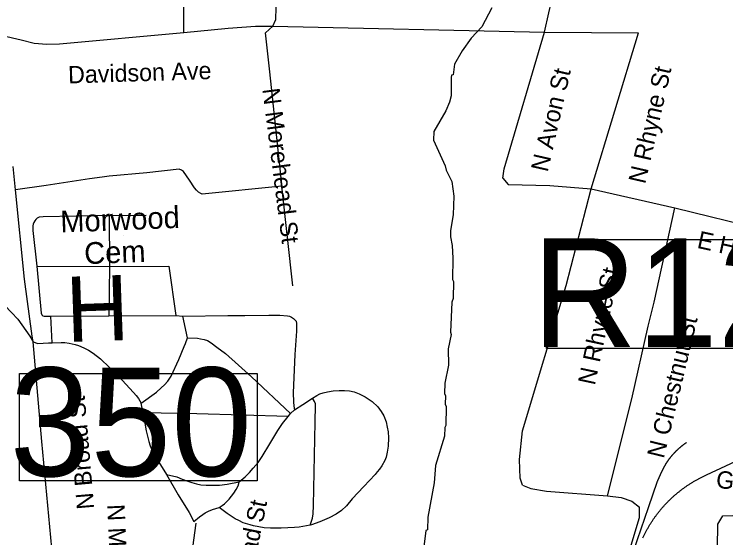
# Model space of a CAD drawing. Extents: x 1268485 to 1426702, y 514839 to 616766.
# Drawn here: x 1350047 to 1352734, y 560205 to 562181 of the extents above; entities that cross this region are included whole.
import ezdxf

# ---------------------------------------------------------------- set-up
doc = ezdxf.new("R2010")
doc.units = 0
for name, color, linetype in [('Old_Level_10', 7, 'Continuous'), ('Old_Level_22', 7, 'Continuous'), ('Old_Level_31', 7, 'Continuous'), ('Old_Level_35', 7, 'Continuous'), ('Old_Level_44', 7, 'Continuous'), ('Old_Level_62', 7, 'Continuous')]:
    doc.layers.add(name, color=color, linetype=linetype)

msp = doc.modelspace()

# ---------------------------------------------------------------- linework, layer by layer
at = {"layer": 'Old_Level_22'}
msp.add_line((1350461.386, 561344.686), (1350461.386, 561344.686), dxfattribs=at)
at = {"layer": 'Old_Level_31'}
for points in [[(1352056.755, 561330.524), (1353320.503, 561330.524), (1353320.503, 560920.201), (1352056.755, 560920.201), (1352056.755, 561330.524)], [(1350067.77, 560825.227), (1350964.648, 560825.227), (1350964.648, 560420.886), (1350067.77, 560420.886), (1350067.77, 560825.227)]]:
    msp.add_lwpolyline(points, dxfattribs=at)
at = {"layer": 'Old_Level_35'}
for p, q in [((1351023.791, 562136.395), (1352049.462, 562113.275)), ((1352049.462, 562113.275), (1352403.894, 562111.379)), ((1352225.089, 561522.007), (1352403.894, 562111.379)), ((1350052.767, 561518.163), (1350043.847, 561606.386)), ((1351098.738, 561156.194), (1351057.727, 561531.85)), ((1352131.483, 561157.374), (1352225.089, 561522.007)), ((1352225.089, 561522.007), (1352541.792, 561450.137)), ((1350405.764, 561421.327), (1350544.995, 561423.48)), ((1352463.359, 561094.115), (1352541.792, 561450.137)), ((1350405.764, 561421.327), (1350406.79, 561229.757)), ((1350132.84, 561230.372), (1350406.79, 561229.757)), ((1350406.79, 561229.757), (1350404.739, 561043.108)), ((1350406.79, 561229.757), (1350631.527, 561230.68)), ((1350631.527, 561230.68), (1350657.978, 561043.775)), ((1352440.291, 561004.508), (1352463.359, 561094.115)), ((1350185.128, 561041.775), (1350404.739, 561043.108)), ((1350191.075, 560941.505), (1350185.128, 561041.775)), ((1350404.739, 561043.108), (1350657.978, 561043.775)), ((1350657.978, 561043.775), (1350683.917, 561041.98)), ((1350701.142, 560960.575), (1350683.917, 561041.98)), ((1350534.742, 560677.039), (1350526.232, 560713.692)), ((1351081.103, 560663.454), (1351090.331, 560674.989)), ((1351090.331, 560674.989), (1351104.992, 560687.753)), ((1350708.524, 560071.982), (1350734.463, 560260.476))]:
    msp.add_line(p, q, dxfattribs=at)
for points in [[(1350687.301, 562112.455), (1350687.301, 562306.178), (1350694.478, 562365.541), (1350708.114, 562428.082), (1350736.206, 562519.688), (1350750.764, 562568.696), (1350760.094, 562614.525), (1350768.501, 562710.336), (1350782.035, 562979.057)], [(1352049.462, 562113.275), (1352065.353, 562186.376), (1352073.76, 562223.901), (1352093.548, 562326.991), (1352106.979, 562417.624), (1352113.233, 562461.351), (1352120.615, 562528.045), (1352121.127, 562567.517), (1352119.487, 562606.169), (1352105.954, 562659.329)], [(1351023.791, 562136.395), (1351035.172, 562161.36), (1351039.375, 562343.703), (1351046.655, 562382.201), (1351083.154, 562478.063)], [(1350687.301, 562112.455), (1350855.033, 562129.064), (1350958.175, 562136.395), (1351023.791, 562136.395)], [(1351057.727, 561531.85), (1351057.01, 561538.463), (1351012.206, 561963.434), (1350995.597, 562110.302), (1351023.791, 562136.395)], [(1350003.247, 562101.126), (1350072.965, 562084.517), (1350122.997, 562072.009), (1350169.852, 562067.805), (1350217.731, 562068.881), (1350687.301, 562112.455)], [(1351891.367, 561562.454), (1351896.903, 561598.082), (1352049.462, 562113.275)], [(1351057.727, 561531.85), (1350756.916, 561501.964), (1350751.79, 561504.117), (1350743.588, 561509.294), (1350734.873, 561517.394), (1350727.491, 561525.442), (1350708.421, 561554.816), (1350686.378, 561587.061), (1350679.099, 561592.955), (1350670.281, 561595.878), (1350547.763, 561582.703), (1350405.354, 561569.477), (1350379.723, 561566.504), (1350331.33, 561559.584), (1350282.836, 561552.56), (1350167.391, 561535.336), (1350052.767, 561518.163)], [(1351891.367, 561562.454), (1351912.282, 561538.463), (1352069.454, 561534.31), (1352225.089, 561522.007)], [(1350118.896, 560944.888), (1350114.795, 560965.753), (1350086.498, 561181.365), (1350052.767, 561518.163)], [(1352541.792, 561450.137), (1352869.875, 561369.859), (1353459.502, 561227.194)], [(1350405.764, 561421.327), (1350157.036, 561416.867), (1350141.452, 561415.022), (1350133.455, 561410.921), (1350128.329, 561407.076), (1350124.843, 561401.642), (1350121.254, 561394.824), (1350118.486, 561388.263), (1350117.256, 561382.829), (1350117.051, 561376.523), (1350117.051, 561365.502), (1350132.84, 561230.372)], [(1350132.84, 561230.372), (1350148.834, 561053.566), (1350151.295, 561047.107), (1350155.601, 561042.75), (1350160.624, 561041.314), (1350185.128, 561041.775)], [(1349750.52, 561156.707), (1349792.146, 561160.245), (1349827.005, 561162.5), (1349862.376, 561162.038), (1349896.722, 561156.81), (1349930.248, 561145.634), (1349960.904, 561128.257), (1349987.15, 561105.547), (1350012.167, 561081.35), (1350036.465, 561056.129), (1350060.457, 561030.447), (1350106.286, 560966.573), (1350118.896, 560944.888)], [(1351965.8, 560404.268), (1351957.393, 560430.31), (1351954.215, 560501.105), (1351965.8, 560609.526), (1352131.483, 561157.374)], [(1350683.917, 561041.98), (1350854.008, 561044.339), (1350918.497, 561043.878), (1351009.027, 561045.261), (1351050.243, 561045.261), (1351078.745, 561043.416), (1351086.23, 561041.673), (1351093.714, 561037.726), (1351101.608, 561033.368), (1351108.17, 561027.166), (1351111.246, 561022.398), (1351112.989, 561014.043), (1351112.476, 560985.078), (1351106.837, 560896.753), (1351099.866, 560752.294), (1351101.096, 560718.921), (1351102.531, 560702.671), (1351104.992, 560687.753)], [(1352287.63, 560363.617), (1352378.263, 560729.276), (1352440.291, 561004.508)], [(1350195.893, 559783.422), (1350203.275, 559888.614), (1350204.096, 559967.815), (1350201.122, 560044.864), (1350151.09, 560568.874), (1350118.896, 560944.888)], [(1350118.896, 560944.888), (1350137.043, 560938.429), (1350176.721, 560940.89), (1350191.075, 560941.505)], [(1350191.075, 560941.505), (1350224.601, 560942.479), (1350237.827, 560942.018), (1350254.538, 560939.814), (1350276.992, 560934.585), (1350289.602, 560931.047), (1350310.62, 560922.692), (1350328.255, 560913.567), (1350345.376, 560902.084), (1350372.956, 560880.554), (1350441.546, 560814.68), (1350498.14, 560754.087), (1350507.88, 560741.989), (1350516.082, 560731.276), (1350526.232, 560713.692)], [(1350526.232, 560713.692), (1350584.16, 560754.959), (1350602.614, 560770.748), (1350615.225, 560783.051), (1350626.708, 560795.815), (1350639.524, 560815.552), (1350668.846, 560877.939), (1350689.454, 560927.049), (1350693.862, 560938.071), (1350701.142, 560960.575)], [(1350701.142, 560960.575), (1350738.974, 560958.371), (1350750.457, 560956.525), (1350763.99, 560953.86), (1350776.396, 560949.502), (1350790.339, 560941.146), (1350812.793, 560925.306), (1350844.371, 560900.751), (1350942.796, 560812.425), (1351090.331, 560674.989)], [(1351172.967, 560731.942), (1351189.883, 560742.451), (1351201.264, 560748.192), (1351213.157, 560753.011), (1351229.766, 560756.497), (1351251.707, 560759.983), (1351274.16, 560761.316), (1351294.255, 560761.726), (1351313.632, 560759.983), (1351330.242, 560756.087), (1351349.619, 560749.064), (1351371.97, 560737.632), (1351398.729, 560719.178), (1351419.849, 560699.851), (1351432.973, 560682.319), (1351443.123, 560665.607), (1351451.017, 560642.744), (1351455.426, 560623.418), (1351458.502, 560605.425), (1351459.732, 560582.203), (1351458.502, 560551.445), (1351455.426, 560528.172), (1351451.53, 560509.255), (1351447.019, 560497.414), (1351435.638, 560477.267), (1351426.411, 560464.503), (1351418.106, 560454.814), (1351409.699, 560444.766), (1351367.151, 560399.501), (1351323.27, 560352.083), (1351301.329, 560326.195), (1351282.464, 560308.202), (1351262.267, 560294.976), (1351236.738, 560280.059), (1351201.674, 560265.141), (1351169.993, 560254.632), (1351164.867, 560253.555)], [(1351104.992, 560687.753), (1351136.775, 560708.463), (1351172.967, 560731.942)], [(1351164.867, 560253.555), (1351173.992, 560279.392), (1351175.735, 560296.053), (1351176.658, 560326.81), (1351183.629, 560642.129), (1351184.45, 560705.798), (1351184.142, 560710.616), (1351181.476, 560720.254), (1351172.967, 560731.942)], [(1351081.103, 560663.454), (1350736.923, 560673.246), (1350534.742, 560677.039)], [(1350534.742, 560677.039), (1350541.509, 560629.775), (1350545.507, 560608.705), (1350550.223, 560588.508), (1350555.965, 560568.413), (1350560.784, 560552.214), (1350566.833, 560537.245), (1350580.981, 560510.435), (1350621.889, 560444.51)], [(1350896.146, 560416.982), (1350919.01, 560435.539), (1350935.619, 560451.79), (1350949.255, 560467.63), (1350967.709, 560489.109), (1350983.088, 560511.511), (1351012.923, 560560.262), (1351042.759, 560610.756), (1351059.88, 560636.234), (1351081.103, 560663.454)], [(1350621.889, 560444.51), (1350661.259, 560434.924), (1350681.969, 560426.978), (1350699.091, 560420.007), (1350717.546, 560414.265), (1350735.488, 560408.575), (1350752.097, 560405.499), (1350772.397, 560403.756), (1350798.234, 560403.756), (1350822.02, 560403.756), (1350851.342, 560407.242), (1350896.146, 560416.982)], [(1350621.889, 560444.51), (1350665.668, 560367.052), (1350708.011, 560300.922), (1350725.235, 560267.396)], [(1350820.585, 560320.197), (1350832.785, 560327.118), (1350841.705, 560333.936), (1350858.622, 560351.263), (1350876.051, 560373.613), (1350885.176, 560388.121), (1350892.353, 560401.757), (1350895.019, 560410.112), (1350896.146, 560416.982)], [(1351965.8, 560404.268), (1351997.994, 560391.76), (1352056.126, 560381.252), (1352287.63, 560363.617)], [(1352287.63, 560363.617), (1352338.585, 560357.363), (1352378.263, 560343.881), (1352407.38, 560320.915)], [(1350725.235, 560267.396), (1350746.253, 560283.955), (1350758.966, 560293.489), (1350768.091, 560299.641), (1350781.215, 560306.203), (1350795.773, 560311.944), (1350820.585, 560320.197)], [(1351164.867, 560253.555), (1351122.626, 560244.943), (1351106.017, 560243.61), (1351055.472, 560241.457), (1351015.077, 560241.867), (1350991.393, 560243.2), (1350950.998, 560250.274), (1350937.464, 560253.863), (1350912.038, 560262.065), (1350894.916, 560270.011), (1350881.28, 560277.444), (1350851.855, 560297.231), (1350820.585, 560320.197)], [(1352340.738, 559924.088), (1352334.484, 559995.959), (1352341.046, 560060.448), (1352407.38, 560281.391), (1352407.38, 560320.915)], [(1352698.964, 559895.944), (1352703.373, 560257.4), (1352722.033, 560288.619)], [(1352722.033, 560288.619), (1352758.532, 560289.696), (1353058.421, 560277.188)]]:
    msp.add_lwpolyline(points, dxfattribs=at)
at = {"layer": 'Old_Level_44'}
for points in [[(1352643.498, 560434.463), (1352661.03, 560442.613), (1353357.899, 560767.775), (1353468.627, 560819.396), (1353573.511, 560868.199), (1354720.983, 561401.949), (1355617.265, 561818.205)], [(1352507.241, 560483.829), (1352507.856, 560484.803), (1352508.471, 560485.726), (1352509.086, 560486.751), (1352509.701, 560487.674), (1352510.419, 560488.647), (1352511.034, 560489.622), (1352511.649, 560490.545), (1352512.264, 560491.518), (1352512.879, 560492.493), (1352513.495, 560493.415), (1352514.11, 560494.389), (1352514.827, 560495.312), (1352515.545, 560496.234), (1352516.16, 560497.209), (1352516.775, 560498.131), (1352517.493, 560499.054), (1352518.108, 560499.977), (1352518.826, 560500.951), (1352519.544, 560501.873), (1352520.159, 560502.796), (1352520.876, 560503.668), (1352521.492, 560504.641), (1352522.209, 560505.513), (1352523.03, 560506.436), (1352523.645, 560507.359), (1352524.362, 560508.23), (1352525.08, 560509.102), (1352525.798, 560510.075), (1352526.515, 560510.947), (1352527.233, 560511.818), (1352527.951, 560512.741), (1352528.668, 560513.613), (1352529.386, 560514.484), (1352530.104, 560515.356), (1352530.924, 560516.227), (1352531.642, 560517.15), (1352532.359, 560518.022), (1352533.077, 560518.893), (1352533.897, 560519.764), (1352534.615, 560520.585), (1352535.333, 560521.456), (1352536.153, 560522.328), (1352536.973, 560523.148), (1352537.793, 560524.019), (1352538.511, 560524.891), (1352539.229, 560525.711), (1352540.049, 560526.48), (1352540.869, 560527.351), (1352541.587, 560528.172), (1352542.407, 560528.992), (1352543.227, 560529.812), (1352544.047, 560530.683), (1352544.868, 560531.503), (1352545.585, 560532.323), (1352546.508, 560533.144), (1352547.226, 560533.913), (1352548.148, 560534.682), (1352548.866, 560535.502), (1352549.789, 560536.322), (1352550.609, 560537.142), (1352551.327, 560537.86), (1352552.249, 560538.68), (1352553.172, 560539.449), (1352553.89, 560540.27), (1352554.71, 560540.987), (1352555.633, 560541.808), (1352556.453, 560542.576), (1352557.376, 560543.294), (1352558.093, 560544.063), (1352559.016, 560544.883), (1352559.836, 560545.601), (1352560.759, 560546.37), (1352561.579, 560547.139), (1352562.502, 560547.805), (1352563.425, 560548.574), (1352564.245, 560549.292), (1352565.168, 560550.06), (1352565.988, 560550.727), (1352566.911, 560551.496), (1352567.833, 560552.214), (1352568.756, 560552.931), (1352569.576, 560553.649), (1352570.499, 560554.367), (1352571.422, 560555.084), (1352572.345, 560555.751), (1352573.267, 560556.417), (1352574.088, 560557.135), (1352575.113, 560557.802), (1352576.035, 560558.519), (1352576.856, 560559.185), (1352577.881, 560559.852), (1352578.701, 560560.57), (1352579.726, 560561.236), (1352580.649, 560561.851), (1352581.674, 560562.569), (1352582.495, 560563.184), (1352583.52, 560563.851), (1352584.34, 560564.517), (1352585.365, 560565.184)], [(1352476.38, 560419.494), (1352476.585, 560420.212), (1352476.995, 560420.878), (1352477.2, 560421.493), (1352477.508, 560422.211), (1352477.713, 560422.877), (1352478.021, 560423.493), (1352478.328, 560424.21), (1352478.636, 560424.876), (1352478.841, 560425.491), (1352479.148, 560426.209), (1352479.456, 560426.876), (1352479.764, 560427.491), (1352479.969, 560428.209), (1352480.276, 560428.824), (1352480.584, 560429.49), (1352480.891, 560430.208), (1352481.096, 560430.823), (1352481.506, 560431.49), (1352481.712, 560432.105), (1352482.019, 560432.822), (1352482.224, 560433.438), (1352482.634, 560434.104), (1352482.839, 560434.77), (1352483.147, 560435.436), (1352483.454, 560436.103), (1352483.762, 560436.769), (1352483.967, 560437.436), (1352484.377, 560438.051), (1352484.582, 560438.769), (1352484.992, 560439.384), (1352485.3, 560440.05), (1352485.505, 560440.665), (1352485.915, 560441.383), (1352486.12, 560441.998), (1352486.53, 560442.665), (1352486.735, 560443.331), (1352487.043, 560443.998), (1352487.35, 560444.613), (1352487.658, 560445.331), (1352487.966, 560445.946), (1352488.273, 560446.561), (1352488.581, 560447.227), (1352488.888, 560447.894), (1352489.093, 560448.56), (1352489.504, 560449.175), (1352489.709, 560449.893), (1352490.119, 560450.508), (1352490.426, 560451.123), (1352490.734, 560451.79), (1352491.041, 560452.456), (1352491.349, 560453.123), (1352491.657, 560453.738), (1352491.964, 560454.353), (1352492.272, 560455.071), (1352492.579, 560455.686), (1352492.887, 560456.301), (1352493.297, 560457.019), (1352493.605, 560457.634), (1352493.912, 560458.3), (1352494.22, 560458.915), (1352494.527, 560459.582), (1352494.835, 560460.248), (1352495.142, 560460.863), (1352495.45, 560461.478), (1352495.758, 560462.145), (1352496.168, 560462.811), (1352496.475, 560463.426), (1352496.783, 560464.041), (1352497.09, 560464.759), (1352497.501, 560465.374), (1352497.706, 560465.989), (1352498.116, 560466.604), (1352498.423, 560467.322), (1352498.731, 560467.937), (1352499.141, 560468.552), (1352499.346, 560469.167), (1352499.756, 560469.885), (1352500.166, 560470.5), (1352500.371, 560471.115), (1352500.781, 560471.731), (1352501.089, 560472.397), (1352501.397, 560473.063), (1352501.704, 560473.679), (1352502.114, 560474.294), (1352502.524, 560474.961), (1352502.729, 560475.576), (1352503.139, 560476.242), (1352503.55, 560476.857), (1352503.755, 560477.524), (1352504.165, 560478.139), (1352504.472, 560478.754), (1352504.882, 560479.369), (1352505.293, 560479.984), (1352505.498, 560480.65), (1352505.908, 560481.317), (1352506.215, 560481.932), (1352506.625, 560482.548), (1352506.83, 560483.214), (1352507.241, 560483.829)], [(1352444.495, 560250.634), (1352445.827, 560252.992), (1352447.365, 560255.401), (1352448.801, 560257.759), (1352450.236, 560260.066), (1352451.774, 560262.424), (1352453.209, 560264.731), (1352454.747, 560267.089), (1352456.285, 560269.396), (1352457.925, 560271.702), (1352459.361, 560274.01), (1352461.001, 560276.316), (1352462.539, 560278.572), (1352464.077, 560280.827), (1352465.717, 560283.134), (1352467.358, 560285.39), (1352468.998, 560287.543), (1352470.639, 560289.799), (1352472.279, 560292.054), (1352474.022, 560294.258), (1352475.663, 560296.463), (1352477.405, 560298.667), (1352479.046, 560300.82), (1352480.789, 560303.024), (1352482.532, 560305.177), (1352484.275, 560307.331), (1352486.018, 560309.484), (1352487.761, 560311.637), (1352489.606, 560313.738), (1352491.349, 560315.891), (1352493.092, 560317.942), (1352495.04, 560320.044), (1352496.885, 560322.145), (1352498.628, 560324.196), (1352500.474, 560326.246), (1352502.422, 560328.297), (1352504.267, 560330.399), (1352506.113, 560332.398), (1352508.163, 560334.397), (1352510.009, 560336.448), (1352511.854, 560338.396), (1352513.905, 560340.395), (1352515.75, 560342.394), (1352517.801, 560344.291), (1352519.749, 560346.239), (1352521.799, 560348.187), (1352523.747, 560350.135), (1352525.798, 560352.083), (1352527.746, 560353.928), (1352529.796, 560355.876), (1352531.744, 560357.773), (1352533.897, 560359.619), (1352535.845, 560361.413), (1352537.998, 560363.31), (1352540.049, 560365.104), (1352542.099, 560367.001), (1352544.252, 560368.744), (1352546.405, 560370.537), (1352548.456, 560372.383), (1352550.609, 560374.126), (1352552.762, 560375.869), (1352554.915, 560377.612), (1352557.171, 560379.355), (1352559.221, 560381.149), (1352561.374, 560382.79), (1352563.63, 560384.481), (1352565.885, 560386.173), (1352568.038, 560387.864), (1352570.294, 560389.556), (1352572.55, 560391.197), (1352574.703, 560392.837), (1352576.958, 560394.426), (1352579.214, 560396.066), (1352581.469, 560397.604), (1352583.725, 560399.245), (1352586.083, 560400.834), (1352588.339, 560402.372), (1352590.594, 560403.858), (1352592.952, 560405.448), (1352595.208, 560406.934), (1352597.668, 560408.421), (1352600.027, 560409.959), (1352602.385, 560411.445), (1352604.64, 560412.881), (1352606.998, 560414.316), (1352609.356, 560415.751), (1352611.715, 560417.187), (1352614.278, 560418.622), (1352616.636, 560420.007), (1352618.994, 560421.39), (1352621.352, 560422.775), (1352623.915, 560424.108), (1352626.273, 560425.441), (1352628.734, 560426.773), (1352631.092, 560428.055), (1352633.655, 560429.387), (1352636.013, 560430.618), (1352638.474, 560431.95), (1352641.037, 560433.181), (1352643.498, 560434.463)], [(1352386.977, 560158.77), (1352441.521, 560319.992), (1352476.38, 560419.494)], [(1352420.503, 560204.753), (1352421.631, 560207.316), (1352422.862, 560209.931), (1352424.092, 560212.545), (1352425.425, 560215.108), (1352426.655, 560217.774), (1352427.885, 560220.337), (1352429.218, 560222.9), (1352430.551, 560225.463), (1352431.884, 560227.975), (1352433.217, 560230.539), (1352434.55, 560233.05), (1352435.882, 560235.613), (1352437.215, 560238.125), (1352438.753, 560240.637), (1352440.086, 560243.2), (1352441.521, 560245.712), (1352442.957, 560248.121), (1352444.495, 560250.634)]]:
    msp.add_lwpolyline(points, dxfattribs=at)
at = {"layer": 'Old_Level_62'}
msp.add_lwpolyline([(1351850.664, 562204.78), (1351812.934, 562133.729), (1351771.924, 562090.719), (1351738.808, 562043.557), (1351709.588, 561992.294), (1351704.564, 561952.412), (1351698.515, 561950.566), (1351696.362, 561942.621), (1351696.67, 561872.596), (1351690.108, 561848.758), (1351677.292, 561817.077), (1351631.463, 561738.235), (1351630.643, 561706.247), (1351674.319, 561609.206), (1351677.907, 561593.11), (1351699.335, 561549.382), (1351707.435, 561495.146), (1351703.846, 561424.454), (1351694.414, 561364.682), (1351693.901, 561340.69), (1351701.078, 561308.548), (1351702.616, 561260.413), (1351702.001, 561180.545), (1351705.794, 561172.445), (1351704.257, 561108.469), (1351699.95, 561094.576), (1351694.312, 560980.927), (1351696.977, 560972.673), (1351686.007, 560917.924), (1351686.212, 560856.921), (1351672.576, 560789.254), (1351671.653, 560749.32), (1351675.447, 560741.221), (1351674.729, 560709.233), (1351678.523, 560701.133), (1351676.78, 560629.16), (1351672.576, 560621.265), (1351671.858, 560589.328), (1351637.102, 560478.19), (1351633.206, 560412.676), (1351608.395, 560282.878), (1351607.267, 560234.947), (1351601.218, 560233.102), (1351593.733, 560171.278)], dxfattribs=at)

# ---------------------------------------------------------------- texts
at = {"layer": 'Old_Level_10'}
for s, height, rotation, p in [('Davidson Ave', 65.61666, 1.778478, (1350251.597, 561919.746)), ('N Avon St', 65.6167, 77.160719, (1352061.062, 561582.885)), ('N Rhyne St', 65.6167, 77.161336, (1352429.173, 561538.147)), ('N Morehead St', 65.61666, 277.269797, (1350983.707, 561898.499)), ('E Harrison Ave', 65.61665, 347.622039, (1352622.044, 561300.008)), ('N Rhyne St', 65.6167, 77.914222, (1352238.9, 560778.459)), ('N Chestnut St', 65.61666, 76.411794, (1352499.231, 560502.062)), ('N Broad St', 65.6167, 94.894131, (1350349.756, 560315.314)), ('Glenview Ave', 65.61666, 353.771561, (1352694.37, 560394.453)), ('N Morehead St', 65.61666, 78.415633, (1350883.892, 559762.35)), ('N Magnolia St', 65.61666, 272.653494, (1350398.309, 560330.676))]:
    msp.add_text(s, height=height, rotation=rotation, dxfattribs=at).set_placement(p)
at = {"layer": 'Old_Level_22'}
for s, height, rotation, p in [('Morwood ', 82.0208, 2.261511, (1350222.793, 561357.19)), ('Cem', 82.0208, 2.261511, (1350313.108, 561237.723)), ('H', 246.062, 1.975686, (1350246.575, 560943.947))]:
    msp.add_text(s, height=height, rotation=rotation, dxfattribs=at).set_placement(p)
at = {"layer": 'Old_Level_31'}
for s, p in [('R129', (1352002.331, 560925.127)), ('350', (1350030.056, 560437.826))]:
    msp.add_text(s, height=410.1042, dxfattribs=at).set_placement(p)

doc.saveas('drawing.dxf')
